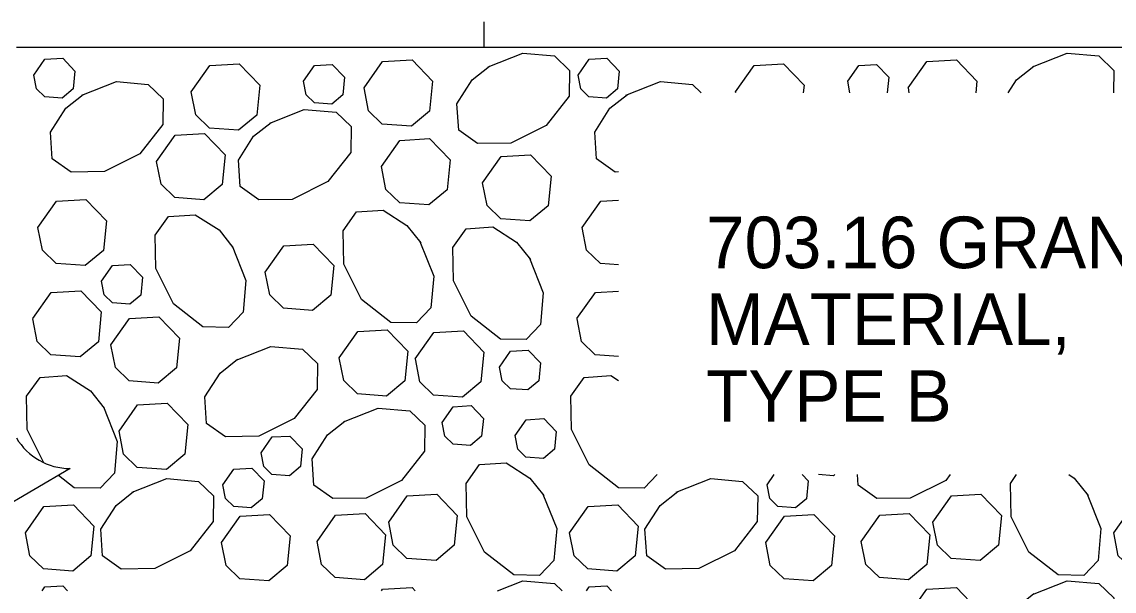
# Model space of a CAD drawing. Extents: x 0 to 34, y 0 to 22.
# Drawn here: x 2.911 to 6.22, y 16.421 to 18.148 of the extents above; entities that cross this region are included whole.
import ezdxf

# ---------------------------------------------------------------- set-up
doc = ezdxf.new("R2010")
doc.units = 0
doc.layers.add('Default', color=7, linetype='Continuous')

msp = doc.modelspace()

# ---------------------------------------------------------------- linework, layer by layer
at = {"layer": 'Default'}
for p, q in [((4.3102, 18.1476), (4.3102, 18.071)), ((2.8946, 18.071), (8.1508, 18.071)), ((3.0568, 16.793), (2.7323, 16.6022))]:
    msp.add_line(p, q, dxfattribs=at)
for points in [[(4.3238, 18.0108), (4.4287, 18.0523), (4.5249, 18.044), (4.5707, 18.0005), (4.5692, 17.9224), (4.4998, 17.8336), (4.3924, 17.78), (4.2913, 17.7782), (4.2344, 17.8187), (4.2289, 17.8992), (4.2752, 17.9713), (4.3281, 18.0135)], [(5.9727, 18.0108), (6.0776, 18.0523), (6.1738, 18.044), (6.2196, 18.0005), (6.2183, 17.9327)], [(2.9473, 17.9861), (2.9809, 18.034), (3.0346, 18.037), (3.0719, 17.9983), (3.0665, 17.9441), (3.0333, 17.9165), (2.9803, 17.9204), (2.9554, 17.9446), (2.9473, 17.9861)], [(3.4244, 17.935), (3.4804, 18.0147), (3.5698, 18.0198), (3.632, 17.9553), (3.623, 17.865), (3.5678, 17.819), (3.4794, 17.8254), (3.4379, 17.8657), (3.4244, 17.935)], [(3.7643, 17.9678), (3.7979, 18.0155), (3.8516, 18.0186), (3.8889, 17.9799), (3.8835, 17.9258), (3.8504, 17.8982), (3.7973, 17.902), (3.7724, 17.9262), (3.7643, 17.9677)], [(3.9479, 17.9471), (4.0039, 18.0268), (4.0934, 18.0319), (4.1555, 17.9674), (4.1465, 17.8771), (4.0913, 17.8311), (4.003, 17.8375), (3.9614, 17.8778), (3.9479, 17.9471)], [(4.5962, 17.9861), (4.6298, 18.034), (4.6835, 18.037), (4.7208, 17.9983), (4.7154, 17.9441), (4.6822, 17.9165), (4.6292, 17.9204), (4.6043, 17.9446), (4.5962, 17.9861)], [(5.0733, 17.935), (5.1293, 18.0147), (5.2187, 18.0198), (5.2809, 17.9553), (5.2787, 17.9327)], [(5.4132, 17.9678), (5.4468, 18.0155), (5.5005, 18.0186), (5.5378, 17.9799), (5.5331, 17.9327)], [(5.5968, 17.9471), (5.6528, 18.0268), (5.7423, 18.0319), (5.8044, 17.9674), (5.801, 17.9327)], [(5.8994, 17.9327), (5.9241, 17.9713), (5.977, 18.0135)], [(3.0924, 17.9248), (3.1972, 17.9663), (3.2935, 17.958), (3.3393, 17.9145), (3.3378, 17.8364), (3.2684, 17.7476), (3.1611, 17.6939), (3.0599, 17.6922), (3.003, 17.7326), (2.9976, 17.8132), (3.0438, 17.8853), (3.0967, 17.9275)], [(4.7414, 17.9248), (4.8462, 17.9663), (4.9424, 17.958), (4.969, 17.9327)], [(5.42, 17.9327), (5.4132, 17.9677)], [(5.5997, 17.9327), (5.5969, 17.9471)], [(4.7191, 17.6923), (4.7088, 17.6922), (4.6519, 17.7326), (4.6465, 17.8132), (4.6927, 17.8853), (4.7456, 17.9275)], [(5.0738, 17.9327), (5.0733, 17.935)], [(3.6618, 17.84), (3.7666, 17.8816), (3.8629, 17.8733), (3.9087, 17.8298), (3.9072, 17.7516), (3.8377, 17.6629), (3.7304, 17.6092), (3.6293, 17.6074), (3.5723, 17.6479), (3.5669, 17.7285), (3.6132, 17.8005), (3.6661, 17.8427)], [(3.3189, 17.7241), (3.375, 17.8038), (3.4644, 17.809), (3.5266, 17.7445), (3.5176, 17.6541), (3.4624, 17.6082), (3.374, 17.6146), (3.3325, 17.6549), (3.319, 17.7241)], [(4.0006, 17.7085), (4.0566, 17.7882), (4.1461, 17.7933), (4.2082, 17.7288), (4.1992, 17.6385), (4.144, 17.5925), (4.0557, 17.5989), (4.0142, 17.6392), (4.0007, 17.7085)], [(4.3069, 17.6597), (4.3629, 17.7394), (4.4524, 17.7445), (4.5145, 17.68), (4.5055, 17.5897), (4.4503, 17.5437), (4.362, 17.5501), (4.3204, 17.5904), (4.3069, 17.6597)], [(2.9597, 17.5242), (3.0157, 17.6039), (3.1052, 17.609), (3.1674, 17.5445), (3.1584, 17.4542), (3.1031, 17.4082), (3.0148, 17.4146), (2.9732, 17.4549), (2.9597, 17.5242)], [(4.1172, 17.4815), (4.1587, 17.3767), (4.1504, 17.2804), (4.1069, 17.2346), (4.0288, 17.2361), (3.94, 17.3055), (3.8864, 17.4129), (3.8846, 17.514), (3.925, 17.571), (4.0056, 17.5763), (4.0777, 17.5302), (4.1199, 17.4773)], [(4.6086, 17.5242), (4.6647, 17.6039), (4.7191, 17.607)], [(3.5478, 17.4679), (3.5894, 17.3631), (3.581, 17.2668), (3.5375, 17.221), (3.4594, 17.2225), (3.3707, 17.292), (3.317, 17.3993), (3.3152, 17.5005), (3.3557, 17.5574), (3.4362, 17.5628), (3.5083, 17.5166), (3.5505, 17.4637)], [(4.4493, 17.4306), (4.4909, 17.3258), (4.4826, 17.2295), (4.4391, 17.1838), (4.3609, 17.1853), (4.2722, 17.2547), (4.2185, 17.362), (4.2167, 17.4632), (4.2572, 17.5201), (4.3377, 17.5255), (4.4098, 17.4793), (4.452, 17.4264)], [(4.7191, 17.4106), (4.6637, 17.4146), (4.6222, 17.4549), (4.6087, 17.5242)], [(3.6484, 17.3886), (3.7044, 17.4683), (3.7939, 17.4734), (3.8561, 17.409), (3.8471, 17.3186), (3.7919, 17.2727), (3.7035, 17.279), (3.662, 17.3193), (3.6485, 17.3886)], [(3.1522, 17.3609), (3.1858, 17.4087), (3.2395, 17.4118), (3.2768, 17.3731), (3.2714, 17.3189), (3.2382, 17.2913), (3.1852, 17.2952), (3.1603, 17.3193), (3.1522, 17.3609)], [(2.944, 17.2475), (3, 17.3271), (3.0895, 17.3323), (3.1517, 17.2678), (3.1427, 17.1774), (3.0874, 17.1315), (2.9991, 17.1379), (2.9575, 17.1782), (2.9441, 17.2474)], [(4.5929, 17.2475), (4.6489, 17.3271), (4.7191, 17.3311)], [(3.1807, 17.1683), (3.2368, 17.248), (3.3262, 17.2531), (3.3884, 17.1887), (3.3794, 17.0983), (3.3242, 17.0523), (3.2358, 17.0588), (3.1943, 17.099), (3.1808, 17.1683)], [(4.7191, 17.1327), (4.648, 17.1379), (4.6064, 17.1782), (4.593, 17.2474)], [(3.8727, 17.1288), (3.9287, 17.2085), (4.0181, 17.2136), (4.0803, 17.1492), (4.0713, 17.0588), (4.016, 17.0129), (3.9277, 17.0193), (3.8862, 17.0595), (3.8727, 17.1288)], [(4.1031, 17.1254), (4.1591, 17.2051), (4.2486, 17.2103), (4.3108, 17.1458), (4.3018, 17.0554), (4.2465, 17.0095), (4.1582, 17.0159), (4.1167, 17.0562), (4.1032, 17.1254)], [(3.5602, 17.1215), (3.6649, 17.1631), (3.7612, 17.1548), (3.807, 17.1113), (3.8055, 17.0331), (3.7361, 16.9444), (3.6287, 16.8907), (3.5276, 16.8889), (3.4707, 16.9294), (3.4653, 17.01), (3.5115, 17.082), (3.5644, 17.1242)], [(4.358, 17.1008), (4.3916, 17.1486), (4.4453, 17.1517), (4.4826, 17.113), (4.4772, 17.0588), (4.4441, 17.0313), (4.3911, 17.0351), (4.3661, 17.0593), (4.358, 17.1008)], [(2.9776, 16.8104), (2.9272, 16.9113), (2.9254, 17.0124), (2.9659, 17.0693), (3.0465, 17.0748), (3.1185, 17.0285), (3.1607, 16.9756)], [(4.8361, 16.7745), (4.7967, 16.733), (4.7186, 16.7345), (4.6298, 16.804), (4.5762, 16.9113), (4.5744, 17.0124), (4.6148, 17.0693), (4.6954, 17.0748), (4.7191, 17.0595)], [(3.158, 16.9799), (3.1996, 16.8751), (3.1913, 16.7788), (3.1478, 16.733), (3.0697, 16.7345), (3.0215, 16.7722)], [(3.2057, 16.9061), (3.2617, 16.9858), (3.3512, 16.9909), (3.4133, 16.9265), (3.4043, 16.8361), (3.3491, 16.7902), (3.2607, 16.7965), (3.2192, 16.8368), (3.2057, 16.9061)], [(4.1846, 16.9327), (4.2182, 16.9805), (4.2719, 16.9836), (4.3092, 16.9449), (4.3038, 16.8907), (4.2707, 16.8631), (4.2177, 16.867), (4.1927, 16.8911), (4.1847, 16.9327)], [(3.8853, 16.9343), (3.9901, 16.9759), (4.0864, 16.9675), (4.1322, 16.924), (4.1307, 16.8459), (4.0612, 16.7571), (3.9539, 16.7035), (3.8528, 16.7017), (3.7958, 16.7422), (3.7904, 16.8228), (3.8366, 16.8948), (3.8895, 16.937)], [(4.4053, 16.8933), (4.4389, 16.9411), (4.4926, 16.9442), (4.5299, 16.9055), (4.5245, 16.8513), (4.4914, 16.8237), (4.4384, 16.8275), (4.4134, 16.8517), (4.4053, 16.8933)], [(3.6356, 16.8408), (3.6692, 16.8886), (3.7229, 16.8916), (3.7602, 16.853), (3.7548, 16.7988), (3.7216, 16.7712), (3.6686, 16.775), (3.6437, 16.7992), (3.6356, 16.8408)], [(3.52, 16.7435), (3.5536, 16.7914), (3.6073, 16.7944), (3.6446, 16.7558), (3.6392, 16.7015), (3.606, 16.674), (3.553, 16.6778), (3.5281, 16.702), (3.52, 16.7435)], [(4.4899, 16.7155), (4.5315, 16.6107), (4.5232, 16.5144), (4.4797, 16.4687), (4.4016, 16.4701), (4.3128, 16.5396), (4.2592, 16.6469), (4.2574, 16.748), (4.2978, 16.805), (4.3784, 16.8104), (4.4504, 16.7642), (4.4927, 16.7113)], [(3.2448, 16.7208), (3.3497, 16.7624), (3.4459, 16.754), (3.4917, 16.7105), (3.4902, 16.6324), (3.4207, 16.5437), (3.3134, 16.49), (3.2123, 16.4882), (3.1554, 16.5287), (3.1499, 16.6093), (3.1962, 16.6813), (3.2491, 16.7235)], [(4.8937, 16.7208), (4.9986, 16.7624), (5.0948, 16.754), (5.1406, 16.7105), (5.1391, 16.6324), (5.0697, 16.5437), (4.9624, 16.49), (4.8612, 16.4882), (4.8043, 16.5287), (4.7989, 16.6093), (4.8451, 16.6813), (4.898, 16.7235)], [(5.1689, 16.7435), (5.1906, 16.7745)], [(5.2754, 16.7745), (5.2935, 16.7558), (5.2881, 16.7015), (5.2549, 16.674), (5.2019, 16.6778), (5.177, 16.702), (5.1689, 16.7435)], [(5.3745, 16.7745), (5.3705, 16.7712), (5.325, 16.7745)], [(5.7237, 16.7745), (5.7102, 16.7571), (5.6028, 16.7035), (5.5017, 16.7017), (5.4447, 16.7422), (5.4426, 16.7745)], [(6.1389, 16.7155), (6.1804, 16.6107), (6.1721, 16.5144), (6.1286, 16.4687), (6.0505, 16.4701), (5.9617, 16.5396), (5.9081, 16.6469), (5.9063, 16.748), (5.925, 16.7745)], [(6.0834, 16.7745), (6.0994, 16.7642), (6.1416, 16.7113)], [(4.0226, 16.6301), (4.0786, 16.7098), (4.168, 16.715), (4.2302, 16.6505), (4.2212, 16.5601), (4.1659, 16.5142), (4.0777, 16.5206), (4.0361, 16.5609), (4.0226, 16.6301)], [(5.6715, 16.6301), (5.7275, 16.7098), (5.8169, 16.715), (5.8792, 16.6505), (5.8702, 16.5601), (5.8149, 16.5142), (5.7266, 16.5206), (5.685, 16.5609), (5.6715, 16.6301)], [(2.9217, 16.598), (2.9778, 16.6777), (3.0672, 16.6828), (3.1294, 16.6183), (3.1204, 16.528), (3.0652, 16.482), (2.9768, 16.4884), (2.9353, 16.5287), (2.9218, 16.598)], [(4.5707, 16.598), (4.6267, 16.6777), (4.7162, 16.6828), (4.7783, 16.6183), (4.7693, 16.528), (4.7141, 16.482), (4.6257, 16.4884), (4.5842, 16.5287), (4.5707, 16.598)], [(6.2196, 16.598), (6.2756, 16.6777), (6.3651, 16.6828), (6.4272, 16.6183), (6.4182, 16.528), (6.363, 16.482), (6.2747, 16.4884), (6.2331, 16.5287), (6.2197, 16.598)], [(3.5162, 16.5684), (3.5723, 16.6481), (3.6617, 16.6532), (3.7239, 16.5888), (3.7149, 16.4984), (3.6597, 16.4524), (3.5713, 16.4588), (3.5298, 16.4991), (3.5163, 16.5684)], [(3.8053, 16.5717), (3.8613, 16.6514), (3.9508, 16.6565), (4.0129, 16.592), (4.0039, 16.5017), (3.9487, 16.4557), (3.8604, 16.4621), (3.8188, 16.5024), (3.8054, 16.5717)], [(5.1652, 16.5684), (5.2212, 16.6481), (5.3107, 16.6532), (5.3728, 16.5888), (5.3638, 16.4984), (5.3086, 16.4524), (5.2202, 16.4588), (5.1787, 16.4991), (5.1652, 16.5684)], [(5.4542, 16.5717), (5.5102, 16.6514), (5.5997, 16.6565), (5.6619, 16.592), (5.6529, 16.5017), (5.5976, 16.4557), (5.5093, 16.4621), (5.4677, 16.5024), (5.4543, 16.5717)], [(4.3524, 16.4222), (4.4287, 16.4524), (4.5249, 16.4441), (4.548, 16.4222)], [(5.9727, 16.4109), (6.0776, 16.4524), (6.1738, 16.4441), (6.2196, 16.4006), (6.2182, 16.3225), (6.1487, 16.2337), (6.0414, 16.18), (5.9402, 16.1783), (5.8833, 16.2188), (5.8779, 16.2993), (5.9241, 16.3714), (5.977, 16.4136)], [(2.9726, 16.4222), (2.9809, 16.434), (3.0346, 16.4371), (3.0489, 16.4222)], [(4.0006, 16.4222), (4.0039, 16.4269), (4.0934, 16.432), (4.1028, 16.4222)], [(4.6215, 16.4222), (4.6298, 16.434), (4.6835, 16.4371), (4.6978, 16.4222)], [(5.5968, 16.3472), (5.6528, 16.4269), (5.7423, 16.432), (5.8044, 16.3675), (5.7954, 16.2772), (5.7402, 16.2312), (5.6519, 16.2376), (5.6103, 16.2779), (5.5969, 16.3472)]]:
    msp.add_lwpolyline(points, dxfattribs=at)
msp.add_arc((3.0568, 16.9812), 0.1882, 210.4422, 270, dxfattribs=at)

# ---------------------------------------------------------------- texts
for s, height, p in [('703.16 GRANULAR', 0.156486, (4.9841, 17.4005)), ('MATERIAL, ', 0.15649, (4.9841, 17.1676)), ('TYPE B', 0.15649, (4.9841, 16.9347))]:
    msp.add_text(s, height=height, rotation=360, dxfattribs=at).set_placement(p)

doc.saveas('drawing.dxf')
